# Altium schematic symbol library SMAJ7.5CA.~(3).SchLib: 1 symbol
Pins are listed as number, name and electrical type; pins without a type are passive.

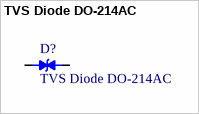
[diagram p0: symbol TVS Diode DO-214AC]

## TVS Diode DO-214AC
designator D?
TVS Diode BiDirectional LittileFuse 1.5SMC6.8CA DO-214AC; MP: SMAJ7.5CA
footprint DIOM4325X250N
pins: 1, 2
